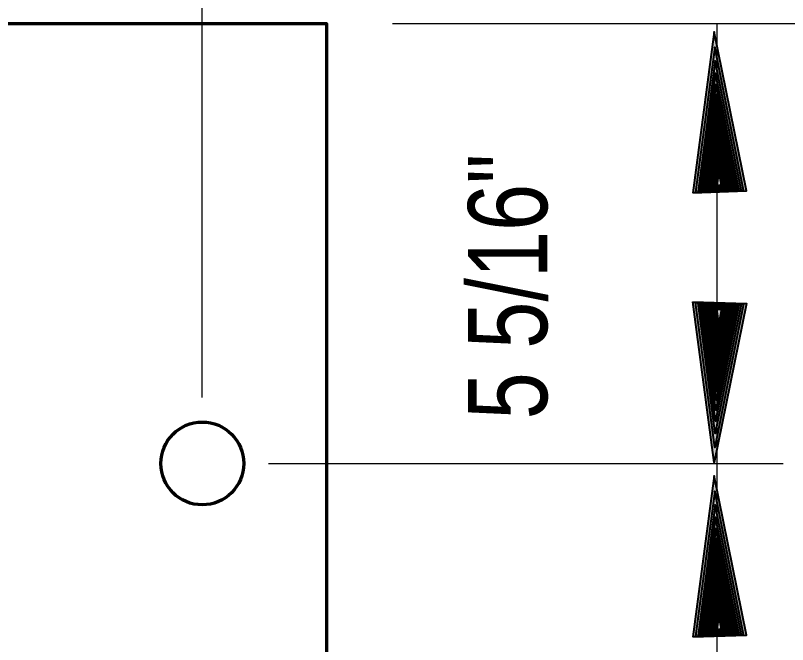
# Model space of a CAD drawing. Extents: x 895.6 to 930.4, y -2278.6 to -2254.7.
# Drawn here: x 902.847 to 904.101, y -2259.945 to -2258.924 of the extents above; entities that cross this region are included whole.
import ezdxf

# ---------------------------------------------------------------- set-up
doc = ezdxf.new("R2010")
doc.units = 0
doc.header["$LTSCALE"] = 0.051
doc.layers.add('1', color=7, linetype='Continuous', lineweight=70)
doc.layers.add('3', color=7, linetype='Continuous', lineweight=40)

msp = doc.modelspace()

# ---------------------------------------------------------------- hatches: boundary and pattern name
at = {"layer": '3'}
for points in [[(903.947, -2259.21192), (904.03367, -2259.209), (903.9815, -2258.95058), (903.9815, -2258.95058)], [(903.95133, -2259.21067), (904.02933, -2259.20792), (903.98233, -2258.97533), (903.98233, -2258.97533)], [(903.95525, -2259.20942), (904.02533, -2259.20708), (903.98308, -2258.99775), (903.98308, -2258.99775)], [(903.95867, -2259.20842), (904.02175, -2259.20625), (903.98375, -2259.01775), (903.98375, -2259.01775)], [(903.96167, -2259.2075), (904.0185, -2259.20558), (903.98433, -2259.03583), (903.98433, -2259.03583)], [(903.96458, -2259.20642), (904.01567, -2259.20483), (903.98483, -2259.05208), (903.98483, -2259.05208)], [(903.96717, -2259.20575), (904.01308, -2259.20425), (903.98533, -2259.06683), (903.98533, -2259.06683)], [(903.96933, -2259.20492), (904.01083, -2259.20367), (903.98583, -2259.08008), (903.98583, -2259.08008)], [(903.97133, -2259.2045), (904.00875, -2259.20317), (903.98633, -2259.09183), (903.98633, -2259.09183)], [(903.97333, -2259.20375), (904.007, -2259.20258), (903.98667, -2259.10267), (903.98667, -2259.10267)], [(903.97483, -2259.20333), (904.00517, -2259.20225), (903.98692, -2259.11225), (903.98692, -2259.11225)], [(903.97642, -2259.20283), (904.00358, -2259.20183), (903.98733, -2259.12083), (903.98733, -2259.12083)], [(903.97775, -2259.20242), (904.00225, -2259.20158), (903.98758, -2259.12875), (903.98758, -2259.12875)], [(903.979, -2259.20183), (904.00108, -2259.20133), (903.98775, -2259.13567), (903.98775, -2259.13567)], [(903.98008, -2259.20167), (903.99992, -2259.201), (903.98792, -2259.14192), (903.98792, -2259.14192)], [(903.98108, -2259.20125), (903.99892, -2259.20083), (903.98825, -2259.14758), (903.98825, -2259.14758)], [(903.982, -2259.20108), (903.99808, -2259.2005), (903.98842, -2259.15267), (903.98842, -2259.15267)], [(903.98283, -2259.20092), (903.99725, -2259.20033), (903.98858, -2259.15725), (903.98858, -2259.15725)], [(903.98325, -2259.2005), (903.99642, -2259.20025), (903.98858, -2259.16133), (903.98858, -2259.16133)], [(903.98383, -2259.20033), (903.99567, -2259.19992), (903.98867, -2259.165), (903.98867, -2259.165)], [(903.98433, -2259.2), (903.99492, -2259.19958), (903.9885, -2259.16825), (903.9885, -2259.16825)], [(903.98492, -2259.2), (903.99433, -2259.19958), (903.98867, -2259.17133), (903.98867, -2259.17133)], [(903.98542, -2259.19983), (903.99392, -2259.1995), (903.98892, -2259.17408), (903.98892, -2259.17408)], [(903.98583, -2259.19958), (903.99342, -2259.19942), (903.98883, -2259.17642), (903.98883, -2259.17642)], [(903.947, -2259.38875), (904.03367, -2259.39167), (903.9815, -2259.65008), (903.9815, -2259.65008)], [(903.95133, -2259.39), (904.02933, -2259.39275), (903.98233, -2259.62533), (903.98233, -2259.62533)], [(903.95525, -2259.39125), (904.02533, -2259.39358), (903.98308, -2259.60292), (903.98308, -2259.60292)], [(903.95867, -2259.39225), (904.02175, -2259.39442), (903.98375, -2259.58292), (903.98375, -2259.58292)], [(903.96167, -2259.39317), (904.0185, -2259.39508), (903.98433, -2259.56483), (903.98433, -2259.56483)], [(903.96458, -2259.39425), (904.01567, -2259.39583), (903.98483, -2259.54858), (903.98483, -2259.54858)], [(903.96717, -2259.39492), (904.01308, -2259.39642), (903.98533, -2259.53383), (903.98533, -2259.53383)], [(903.96933, -2259.39575), (904.01083, -2259.397), (903.98583, -2259.52058), (903.98583, -2259.52058)], [(903.97133, -2259.39617), (904.00875, -2259.3975), (903.98633, -2259.50883), (903.98633, -2259.50883)], [(903.97333, -2259.39692), (904.007, -2259.39808), (903.98667, -2259.498), (903.98667, -2259.498)], [(903.97483, -2259.39733), (904.00517, -2259.39842), (903.98692, -2259.48842), (903.98692, -2259.48842)], [(903.97642, -2259.39783), (904.00358, -2259.39883), (903.98733, -2259.47983), (903.98733, -2259.47983)], [(903.97775, -2259.39825), (904.00225, -2259.39908), (903.98758, -2259.47192), (903.98758, -2259.47192)], [(903.979, -2259.39883), (904.00108, -2259.39933), (903.98775, -2259.465), (903.98775, -2259.465)], [(903.98008, -2259.399), (903.99992, -2259.39967), (903.98792, -2259.45875), (903.98792, -2259.45875)], [(903.98108, -2259.39942), (903.99892, -2259.39983), (903.98825, -2259.45308), (903.98825, -2259.45308)], [(903.982, -2259.39958), (903.99808, -2259.40017), (903.98842, -2259.448), (903.98842, -2259.448)], [(903.98283, -2259.39975), (903.99725, -2259.40033), (903.98858, -2259.44342), (903.98858, -2259.44342)], [(903.98325, -2259.40017), (903.99642, -2259.40042), (903.98858, -2259.43933), (903.98858, -2259.43933)], [(903.98383, -2259.40033), (903.99567, -2259.40075), (903.98867, -2259.43567), (903.98867, -2259.43567)], [(903.98433, -2259.40067), (903.99492, -2259.40108), (903.9885, -2259.43242), (903.9885, -2259.43242)], [(903.98492, -2259.40067), (903.99433, -2259.40108), (903.98867, -2259.42933), (903.98867, -2259.42933)], [(903.98542, -2259.40083), (903.99392, -2259.40117), (903.98892, -2259.42658), (903.98892, -2259.42658)], [(903.98583, -2259.40108), (903.99342, -2259.40125), (903.98883, -2259.42425), (903.98883, -2259.42425)], [(903.947, -2259.93292), (904.03367, -2259.93), (903.9815, -2259.67158), (903.9815, -2259.67158)], [(903.95133, -2259.93167), (904.02933, -2259.92892), (903.98233, -2259.69633), (903.98233, -2259.69633)], [(903.95525, -2259.93042), (904.02533, -2259.92808), (903.98308, -2259.71875), (903.98308, -2259.71875)], [(903.95867, -2259.92942), (904.02175, -2259.92725), (903.98375, -2259.73875), (903.98375, -2259.73875)], [(903.96167, -2259.9285), (904.0185, -2259.92658), (903.98433, -2259.75683), (903.98433, -2259.75683)], [(903.96458, -2259.92742), (904.01567, -2259.92583), (903.98483, -2259.77308), (903.98483, -2259.77308)], [(903.96717, -2259.92675), (904.01308, -2259.92525), (903.98533, -2259.78783), (903.98533, -2259.78783)], [(903.96933, -2259.92592), (904.01083, -2259.92467), (903.98583, -2259.80108), (903.98583, -2259.80108)], [(903.97133, -2259.9255), (904.00875, -2259.92417), (903.98633, -2259.81283), (903.98633, -2259.81283)], [(903.97333, -2259.92475), (904.007, -2259.92358), (903.98667, -2259.82367), (903.98667, -2259.82367)], [(903.97483, -2259.92433), (904.00517, -2259.92325), (903.98692, -2259.83325), (903.98692, -2259.83325)], [(903.97642, -2259.92383), (904.00358, -2259.92283), (903.98733, -2259.84183), (903.98733, -2259.84183)], [(903.97775, -2259.92342), (904.00225, -2259.92258), (903.98758, -2259.84975), (903.98758, -2259.84975)], [(903.979, -2259.92283), (904.00108, -2259.92233), (903.98775, -2259.85667), (903.98775, -2259.85667)], [(903.98008, -2259.92267), (903.99992, -2259.922), (903.98792, -2259.86292), (903.98792, -2259.86292)], [(903.98108, -2259.92225), (903.99892, -2259.92183), (903.98825, -2259.86858), (903.98825, -2259.86858)], [(903.982, -2259.92208), (903.99808, -2259.9215), (903.98842, -2259.87367), (903.98842, -2259.87367)], [(903.98283, -2259.92192), (903.99725, -2259.92133), (903.98858, -2259.87825), (903.98858, -2259.87825)], [(903.98325, -2259.9215), (903.99642, -2259.92125), (903.98858, -2259.88233), (903.98858, -2259.88233)], [(903.98383, -2259.92133), (903.99567, -2259.92092), (903.98867, -2259.886), (903.98867, -2259.886)], [(903.98433, -2259.921), (903.99492, -2259.92058), (903.9885, -2259.88925), (903.9885, -2259.88925)], [(903.98492, -2259.921), (903.99433, -2259.92058), (903.98867, -2259.89233), (903.98867, -2259.89233)], [(903.98542, -2259.92083), (903.99392, -2259.9205), (903.98892, -2259.89508), (903.98892, -2259.89508)], [(903.98583, -2259.92058), (903.99342, -2259.92042), (903.98883, -2259.89742), (903.98883, -2259.89742)]]:
    msp.add_hatch(color=256, dxfattribs=at).paths.add_polyline_path(points)

# ---------------------------------------------------------------- linework, layer by layer
at = {"layer": '1', "lineweight": 25}
for p, q in [((903.15042, -2259.54417), (903.15042, -2258.39383)), ((903.45942, -2258.93683), (904.0935, -2258.93683)), ((903.45942, -2258.93683), (904.738, -2258.93683)), ((903.98608, -2259.65142), (903.98608, -2258.93683)), ((903.25775, -2259.65142), (904.0935, -2259.65142)), ((903.98608, -2260.29758), (903.98608, -2259.65142))]:
    msp.add_line(p, q, dxfattribs=at)
at = {"layer": '1'}
msp.add_lwpolyline([(901.87267, -2258.93683), (903.35208, -2258.93683), (903.35208, -2261.39058)], dxfattribs=at)
msp.add_circle((903.15042, -2259.65145), 0.06722, dxfattribs=at)
at = {"layer": '3'}
for points in [[(903.947, -2259.21192), (904.03367, -2259.209), (903.9815, -2258.95058), (903.9815, -2258.95058)], [(903.95133, -2259.21067), (904.02933, -2259.20792), (903.98233, -2258.97533), (903.98233, -2258.97533)], [(903.95525, -2259.20942), (904.02533, -2259.20708), (903.98308, -2258.99775), (903.98308, -2258.99775)], [(903.95867, -2259.20842), (904.02175, -2259.20625), (903.98375, -2259.01775), (903.98375, -2259.01775)], [(903.96167, -2259.2075), (904.0185, -2259.20558), (903.98433, -2259.03583), (903.98433, -2259.03583)], [(903.96458, -2259.20642), (904.01567, -2259.20483), (903.98483, -2259.05208), (903.98483, -2259.05208)], [(903.96717, -2259.20575), (904.01308, -2259.20425), (903.98533, -2259.06683), (903.98533, -2259.06683)], [(903.96933, -2259.20492), (904.01083, -2259.20367), (903.98583, -2259.08008), (903.98583, -2259.08008)], [(903.97133, -2259.2045), (904.00875, -2259.20317), (903.98633, -2259.09183), (903.98633, -2259.09183)], [(903.97333, -2259.20375), (904.007, -2259.20258), (903.98667, -2259.10267), (903.98667, -2259.10267)], [(903.97483, -2259.20333), (904.00517, -2259.20225), (903.98692, -2259.11225), (903.98692, -2259.11225)], [(903.97642, -2259.20283), (904.00358, -2259.20183), (903.98733, -2259.12083), (903.98733, -2259.12083)], [(903.97775, -2259.20242), (904.00225, -2259.20158), (903.98758, -2259.12875), (903.98758, -2259.12875)], [(903.979, -2259.20183), (904.00108, -2259.20133), (903.98775, -2259.13567), (903.98775, -2259.13567)], [(903.98008, -2259.20167), (903.99992, -2259.201), (903.98792, -2259.14192), (903.98792, -2259.14192)], [(903.98108, -2259.20125), (903.99892, -2259.20083), (903.98825, -2259.14758), (903.98825, -2259.14758)], [(903.982, -2259.20108), (903.99808, -2259.2005), (903.98842, -2259.15267), (903.98842, -2259.15267)], [(903.98283, -2259.20092), (903.99725, -2259.20033), (903.98858, -2259.15725), (903.98858, -2259.15725)], [(903.98325, -2259.2005), (903.99642, -2259.20025), (903.98858, -2259.16133), (903.98858, -2259.16133)], [(903.98383, -2259.20033), (903.99567, -2259.19992), (903.98867, -2259.165), (903.98867, -2259.165)], [(903.98433, -2259.2), (903.99492, -2259.19958), (903.9885, -2259.16825), (903.9885, -2259.16825)], [(903.98492, -2259.2), (903.99433, -2259.19958), (903.98867, -2259.17133), (903.98867, -2259.17133)], [(903.98542, -2259.19983), (903.99392, -2259.1995), (903.98892, -2259.17408), (903.98892, -2259.17408)], [(903.98583, -2259.19958), (903.99342, -2259.19942), (903.98883, -2259.17642), (903.98883, -2259.17642)], [(903.947, -2259.38875), (904.03367, -2259.39167), (903.9815, -2259.65008), (903.9815, -2259.65008)], [(903.95133, -2259.39), (904.02933, -2259.39275), (903.98233, -2259.62533), (903.98233, -2259.62533)], [(903.95525, -2259.39125), (904.02533, -2259.39358), (903.98308, -2259.60292), (903.98308, -2259.60292)], [(903.95867, -2259.39225), (904.02175, -2259.39442), (903.98375, -2259.58292), (903.98375, -2259.58292)], [(903.96167, -2259.39317), (904.0185, -2259.39508), (903.98433, -2259.56483), (903.98433, -2259.56483)], [(903.96458, -2259.39425), (904.01567, -2259.39583), (903.98483, -2259.54858), (903.98483, -2259.54858)], [(903.96717, -2259.39492), (904.01308, -2259.39642), (903.98533, -2259.53383), (903.98533, -2259.53383)], [(903.96933, -2259.39575), (904.01083, -2259.397), (903.98583, -2259.52058), (903.98583, -2259.52058)], [(903.97133, -2259.39617), (904.00875, -2259.3975), (903.98633, -2259.50883), (903.98633, -2259.50883)], [(903.97333, -2259.39692), (904.007, -2259.39808), (903.98667, -2259.498), (903.98667, -2259.498)], [(903.97483, -2259.39733), (904.00517, -2259.39842), (903.98692, -2259.48842), (903.98692, -2259.48842)], [(903.97642, -2259.39783), (904.00358, -2259.39883), (903.98733, -2259.47983), (903.98733, -2259.47983)], [(903.97775, -2259.39825), (904.00225, -2259.39908), (903.98758, -2259.47192), (903.98758, -2259.47192)], [(903.979, -2259.39883), (904.00108, -2259.39933), (903.98775, -2259.465), (903.98775, -2259.465)], [(903.98008, -2259.399), (903.99992, -2259.39967), (903.98792, -2259.45875), (903.98792, -2259.45875)], [(903.98108, -2259.39942), (903.99892, -2259.39983), (903.98825, -2259.45308), (903.98825, -2259.45308)], [(903.982, -2259.39958), (903.99808, -2259.40017), (903.98842, -2259.448), (903.98842, -2259.448)], [(903.98283, -2259.39975), (903.99725, -2259.40033), (903.98858, -2259.44342), (903.98858, -2259.44342)], [(903.98325, -2259.40017), (903.99642, -2259.40042), (903.98858, -2259.43933), (903.98858, -2259.43933)], [(903.98383, -2259.40033), (903.99567, -2259.40075), (903.98867, -2259.43567), (903.98867, -2259.43567)], [(903.98433, -2259.40067), (903.99492, -2259.40108), (903.9885, -2259.43242), (903.9885, -2259.43242)], [(903.98492, -2259.40067), (903.99433, -2259.40108), (903.98867, -2259.42933), (903.98867, -2259.42933)], [(903.98542, -2259.40083), (903.99392, -2259.40117), (903.98892, -2259.42658), (903.98892, -2259.42658)], [(903.98583, -2259.40108), (903.99342, -2259.40125), (903.98883, -2259.42425), (903.98883, -2259.42425)], [(903.947, -2259.93292), (904.03367, -2259.93), (903.9815, -2259.67158), (903.9815, -2259.67158)], [(903.95133, -2259.93167), (904.02933, -2259.92892), (903.98233, -2259.69633), (903.98233, -2259.69633)], [(903.95525, -2259.93042), (904.02533, -2259.92808), (903.98308, -2259.71875), (903.98308, -2259.71875)], [(903.95867, -2259.92942), (904.02175, -2259.92725), (903.98375, -2259.73875), (903.98375, -2259.73875)], [(903.96167, -2259.9285), (904.0185, -2259.92658), (903.98433, -2259.75683), (903.98433, -2259.75683)], [(903.96458, -2259.92742), (904.01567, -2259.92583), (903.98483, -2259.77308), (903.98483, -2259.77308)], [(903.96717, -2259.92675), (904.01308, -2259.92525), (903.98533, -2259.78783), (903.98533, -2259.78783)], [(903.96933, -2259.92592), (904.01083, -2259.92467), (903.98583, -2259.80108), (903.98583, -2259.80108)], [(903.97133, -2259.9255), (904.00875, -2259.92417), (903.98633, -2259.81283), (903.98633, -2259.81283)], [(903.97333, -2259.92475), (904.007, -2259.92358), (903.98667, -2259.82367), (903.98667, -2259.82367)], [(903.97483, -2259.92433), (904.00517, -2259.92325), (903.98692, -2259.83325), (903.98692, -2259.83325)], [(903.97642, -2259.92383), (904.00358, -2259.92283), (903.98733, -2259.84183), (903.98733, -2259.84183)], [(903.97775, -2259.92342), (904.00225, -2259.92258), (903.98758, -2259.84975), (903.98758, -2259.84975)], [(903.979, -2259.92283), (904.00108, -2259.92233), (903.98775, -2259.85667), (903.98775, -2259.85667)], [(903.98008, -2259.92267), (903.99992, -2259.922), (903.98792, -2259.86292), (903.98792, -2259.86292)], [(903.98108, -2259.92225), (903.99892, -2259.92183), (903.98825, -2259.86858), (903.98825, -2259.86858)], [(903.982, -2259.92208), (903.99808, -2259.9215), (903.98842, -2259.87367), (903.98842, -2259.87367)], [(903.98283, -2259.92192), (903.99725, -2259.92133), (903.98858, -2259.87825), (903.98858, -2259.87825)], [(903.98325, -2259.9215), (903.99642, -2259.92125), (903.98858, -2259.88233), (903.98858, -2259.88233)], [(903.98383, -2259.92133), (903.99567, -2259.92092), (903.98867, -2259.886), (903.98867, -2259.886)], [(903.98433, -2259.921), (903.99492, -2259.92058), (903.9885, -2259.88925), (903.9885, -2259.88925)], [(903.98492, -2259.921), (903.99433, -2259.92058), (903.98867, -2259.89233), (903.98867, -2259.89233)], [(903.98542, -2259.92083), (903.99392, -2259.9205), (903.98892, -2259.89508), (903.98892, -2259.89508)], [(903.98583, -2259.92058), (903.99342, -2259.92042), (903.98883, -2259.89742), (903.98883, -2259.89742)]]:
    msp.add_lwpolyline(points, close=True, dxfattribs=at)

# ---------------------------------------------------------------- texts
at = {"layer": '1', "width": 0.8}
msp.add_text('5 5/16"', height=0.1286, rotation=90, dxfattribs=at).set_placement((903.71042, -2259.57983))

doc.saveas('drawing.dxf')
